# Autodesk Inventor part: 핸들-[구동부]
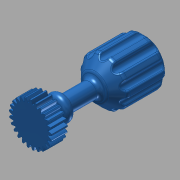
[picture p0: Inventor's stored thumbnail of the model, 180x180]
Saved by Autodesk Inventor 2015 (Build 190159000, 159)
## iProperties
Created: 2017-04
Part Number: 핸들-[구동부]
Material: 강철, 연강
Document SubType Name: Modeling
Designer: mduedu
Categories: <?xml version="1.0" encoding="UTF-16"?> <MemberInstance><Categories><FamilyTemplate><FamilyTemplateParameter ValueType="xs:double" Id="1" ObjectReferenceKey="da
Density: 7.86 g/cm^3
Appearance: 청록색
Mass: 209.32 g
Surface Area: 78.6033 cm^2
Volume: 26.631 cm^3
CustomPartVersion: 1
Author: mduedu
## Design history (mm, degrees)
sketch "Sketch1"
  geometry: C1 r 13.5 at (0, 0)
  constraints: 1 centre point
  dimensions: "d0" = 27 diameter of C1 (= da_da)
extrude "Extrusion1" new body sketch "Sketch1" distance "d1" = 10 (= da_b); taper "d2" = 0 deg
workplane "Work Plane2"
sketch "Sketch2"
  geometry: C1 r 13.5 at (0, 0) reference; C2 r 12.5 at (0, 0)
  constraints: 1 centre point, 1 coincident
  dimensions: "d3" = 25 diameter of C2 (= da_dw)
feature "피치 지름" sketch "Sketch2" dims "d4" = 10, "d5" = 0
workplane "Work Plane8"
workplane "Work Plane9"
feature "스퍼 기어" dims "da_b" = 10, "da_d" = 25, "da_aw" = 25, "da_da" = 27, "da_df" = 22.5, "da_dw" = 25, angle "da_beta" = 0 deg, "da_lefttooth" = 0, "da_righttooth" = 0
sketch "스케치3"
  geometry: C1 r 5 at (0, 0); 1 further point
  constraints: 1 centre point, 1 coincident
  dimensions: "d49" = 10 diameter of C1
extrude "돌출2" join sketch "스케치3" distance "d50" = 60; taper "d51" = 0 deg
sketch "스케치4"
  geometry: C1 r 15 at (0, 0); 1 further point
  constraints: 1 centre point, 1 coincident
  dimensions: "d52" = 30 diameter of C1
extrude "돌출3" join sketch "스케치4" distance "d53" = 30; taper "d54" = 0 deg
chamfer "모따기1" distance "d55" = 7; stored, may be unused: second distance "d56" = 2, angle "d57" = 45 deg
sketch "스케치5"
  geometry: L1 (0, 2.2)-(0, -13.2) reference; L2 (0, -5)-(8, -5); L3 (8, -5)-(8, -11); L4 (8, -11)-(0, -11); L5 (0, -11)-(0, -5); 1 further point
  constraints: 8 end point, 2 parallel, 1 horizontal, 1 perpendicular, 1 point on line
  dimensions: "d58" = 5 distance from line of L2 point (0, 0); "d59" = 6 distance of L2.end L3.end; "d60" = 16 diameter of L3 L1
revolve "회전1" sketch "스케치5" stored, may be unused: angle "d61" = 90 deg
fillet "모깎기1" dims "d62" = 3
fillet "모깎기2" dims "d65" = 3
sketch "스케치9"
  geometry: L1 (15, -60)-(-15, -60) reference; L2 (0, -60)-(0, 0); L3 (0, -66.771)-(0, -60); A1 r 20 centre (0, -46.771) between (0, -66.771) and (15, -60)
  constraints: 4 end point, 2 point on circle, 1 centre point, 1 collinear, 1 line through centre, 1 midpoint, 1 perpendicular
  dimensions: "d84" = 20 radius of A1
revolve "회전4" sketch "스케치9" stored, may be unused: angle "d86" = 90 deg
fillet "모깎기3" dims "d72" = 3
sketch "스케치6"
  geometry: C1 r 2.5 at (0, 15); 2 further points
  constraints: 2 vertical alignment, 1 centre point, 1 other
  dimensions: "d66" = 5 diameter of C1
extrude "돌출4" cut sketch "스케치6" stored distance "d67" = 60; taper "d68" = 0 deg
fillet "모깎기4" dims "d73" = 1
node "작업 평면12"
sketch "스케치10"
  geometry: C1 r 6 at (0, 0); 1 further point
  constraints: 1 centre point, 1 coincident
  dimensions: "d87" = 12 diameter of C1
extrude "돌출5" cut sketch "스케치10" distance "d88" = 5; taper "d89" = 0 deg
fillet "모깎기5" dims "d90" = 1
body "Solid1"
pattern_circular "원형 패턴2" dims angle "d75" = 360 deg
body "Srf1"
other parameters: "d16" = 25 (= da_aw), "d17" = 0, "d34" = 1.25664 (computed from da_z), "d39" = 0, "d41" = 0, "d43" = 25 (= da_aw), "d46" = 25 (= da_aw), "d47" = 0, "d48" = 0
